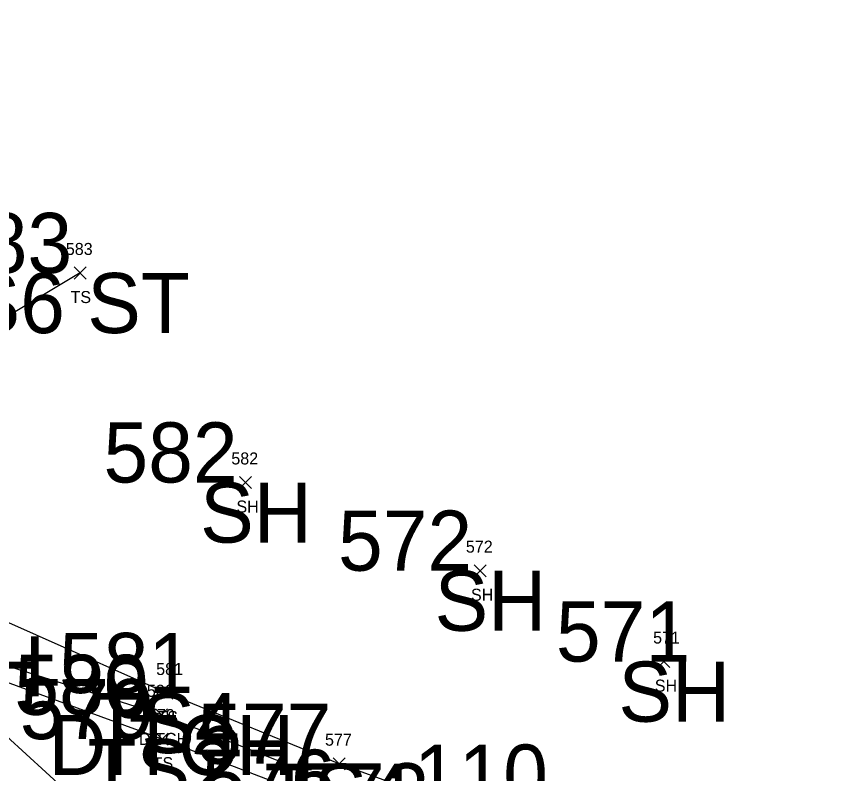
# Model space of a CAD drawing. Extents: x 1616840 to 1618410, y 488554 to 491945.
# Drawn here: x 1618236.2 to 1618372.7, y 488744.1 to 488870 of the extents above; entities that cross this region are included whole.
import ezdxf

# ---------------------------------------------------------------- set-up
doc = ezdxf.new("R2010")
doc.units = 0
for name, color, linetype in [('C_A', 7, 'Continuous'), ('C_I', 7, 'Continuous'), ('D_A', 7, 'Continuous'), ('D_I', 7, 'Continuous'), ('D_TIC', 7, 'Continuous'), ('DD', 7, 'Continuous'), ('L_A', 7, 'Continuous'), ('L_I', 7, 'Continuous'), ('L_TIC', 7, 'Continuous'), ('LELB', 7, 'Continuous')]:
    doc.layers.add(name, color=color, linetype=linetype)

msp = doc.modelspace()

# ---------------------------------------------------------------- linework, layer by layer
at = {"layer": 'D_TIC'}
for points in [[(1618259.33, 488752.83), (1618261.33, 488754.83)], [(1618261.33, 488752.83), (1618259.33, 488754.83)]]:
    msp.add_lwpolyline(points, dxfattribs=at)
at = {"layer": 'DD'}
msp.add_lwpolyline([(1618334.32, 488725.5), (1618306.17, 488735.78), (1618260.33, 488753.83), (1618218.93, 488766.9), (1618185.78, 488782.47), (1618159.33, 488797.45), (1618141.33, 488807.73), (1618125.06, 488820.25), (1618102.03, 488843.81)], dxfattribs=at)
msp.add_lwpolyline([(1618334.32, 488725.5), (1618306.17, 488735.78), (1618260.33, 488753.83), (1618218.93, 488766.9), (1618185.78, 488782.47), (1618159.33, 488797.45), (1618141.33, 488807.73), (1618125.06, 488820.25), (1618102.03, 488843.81)], dxfattribs=at)
at = {"layer": 'L_TIC'}
for points in [[(1618245.77, 488826.33), (1618247.77, 488828.33)], [(1618247.77, 488826.33), (1618245.77, 488828.33)], [(1618273.29, 488791.48), (1618275.29, 488793.48)], [(1618275.29, 488791.48), (1618273.29, 488793.48)], [(1618312.28, 488776.81), (1618314.28, 488778.81)], [(1618314.28, 488776.81), (1618312.28, 488778.81)], [(1618342.85, 488761.69), (1618344.85, 488763.69)], [(1618344.85, 488761.69), (1618342.85, 488763.69)], [(1618260.22, 488756.46), (1618262.22, 488758.46)], [(1618262.22, 488756.46), (1618260.22, 488758.46)], [(1618259.44, 488748.79), (1618261.44, 488750.79)], [(1618261.44, 488748.79), (1618259.44, 488750.79)], [(1618288.86, 488744.7), (1618290.86, 488746.7)], [(1618290.86, 488744.7), (1618288.86, 488746.7)]]:
    msp.add_lwpolyline(points, dxfattribs=at)
at = {"layer": 'LELB'}
for points in [[(1618335.13, 488729.22), (1618289.86, 488745.7), (1618261.22, 488757.46), (1618217.81, 488776.75), (1618188.12, 488785.9), (1618183.26, 488803.15), (1618167.49, 488806.5), (1618138.61, 488813.88), (1618120.24, 488832.87), (1618101.99, 488848.67), (1618101.83, 488860.48), (1618116.51, 488870.01)], [(1618335.13, 488729.22), (1618289.86, 488745.7), (1618261.22, 488757.46), (1618217.81, 488776.75), (1618188.12, 488785.9), (1618183.26, 488803.15), (1618167.49, 488806.5), (1618138.61, 488813.88), (1618120.24, 488832.87), (1618101.99, 488848.67), (1618101.83, 488860.48), (1618116.51, 488870.01)], [(1618330.66, 488723.42), (1618291.12, 488738.04), (1618260.44, 488749.79), (1618218.11, 488765.28), (1618192.27, 488774.91), (1618159.3, 488795.39), (1618153.57, 488798.41), (1618138.2, 488806.83), (1618124.27, 488818.44), (1618107.6, 488832.68), (1618102.03, 488843.81)], [(1618330.66, 488723.42), (1618291.12, 488738.04), (1618260.44, 488749.79), (1618218.11, 488765.28), (1618192.27, 488774.91), (1618159.3, 488795.39), (1618153.57, 488798.41), (1618138.2, 488806.83), (1618124.27, 488818.44), (1618107.6, 488832.68), (1618102.03, 488843.81)], [(1618246.77, 488827.33), (1618219.84, 488811.24), (1618183.26, 488803.15), (1618189.92, 488820.41), (1618161.04, 488833.24), (1618167.49, 488806.5)], [(1618246.77, 488827.33), (1618219.84, 488811.24), (1618183.26, 488803.15), (1618189.92, 488820.41), (1618161.04, 488833.24), (1618167.49, 488806.5)], [(1618372.73, 488669.19), (1618328.1, 488689.57), (1618302.14, 488707.09), (1618254.13, 488732.3), (1618218.11, 488765.28)], [(1618372.73, 488669.19), (1618328.1, 488689.57), (1618302.14, 488707.09), (1618254.13, 488732.3), (1618218.11, 488765.28)]]:
    msp.add_lwpolyline(points, dxfattribs=at)

# ---------------------------------------------------------------- texts
at = {"layer": 'C_A'}
for s, p in [('TS6 ST', (1618219.72, 488817.33)), ('SH', (1618266.73, 488782.48)), ('SH', (1618305.72, 488767.81)), ('DITCH', (1618200.11, 488756.9)), ('SH', (1618336.29, 488752.69)), ('TS4', (1618248.77, 488747.46)), ('DITCH', (1618241.51, 488743.83)), ('TS2', (1618247.99, 488739.79)), ('TS4', (1618277.42, 488735.7))]:
    msp.add_text(s, height=10, dxfattribs=at).set_placement(p)
at = {"layer": 'C_I'}
for s, p in [('583', (1618223.14, 488827.33)), ('582', (1618250.66, 488792.48)), ('572', (1618289.66, 488777.81)), ('571', (1618325.9, 488762.69)), ('581', (1618243.26, 488757.46)), ('580', (1618235.84, 488753.83)), ('579', (1618236.73, 488749.79)), ('577', (1618266.24, 488745.7)), ('110', (1618302.26, 488738.89)), ('576', (1618266.95, 488738.04)), ('573', (1618282.54, 488735.78))]:
    msp.add_text(s, height=10, dxfattribs=at).set_placement(p)
at = {"layer": 'D_A'}
msp.add_text('DITCH', height=2, dxfattribs=at).set_placement((1618256.57, 488748.83))
at = {"layer": 'D_I'}
msp.add_text('580', height=2, dxfattribs=at).set_placement((1618257.88, 488756.83))
at = {"layer": 'L_A'}
for s, p in [('TS', (1618245.18, 488822.33)), ('SH', (1618272.77, 488787.48)), ('SH', (1618311.77, 488772.81)), ('SH', (1618342.34, 488757.69)), ('TS', (1618259.63, 488752.46)), ('TS', (1618258.84, 488744.79))]:
    msp.add_text(s, height=2, dxfattribs=at).set_placement(p)
at = {"layer": 'L_I'}
for s, p in [('583', (1618244.4, 488830.33)), ('582', (1618271.92, 488795.48)), ('572', (1618310.92, 488780.81)), ('571', (1618342.06, 488765.69)), ('581', (1618259.42, 488760.46)), ('579', (1618258.06, 488752.79)), ('577', (1618287.5, 488748.7))]:
    msp.add_text(s, height=2, dxfattribs=at).set_placement(p)

doc.saveas('drawing.dxf')
